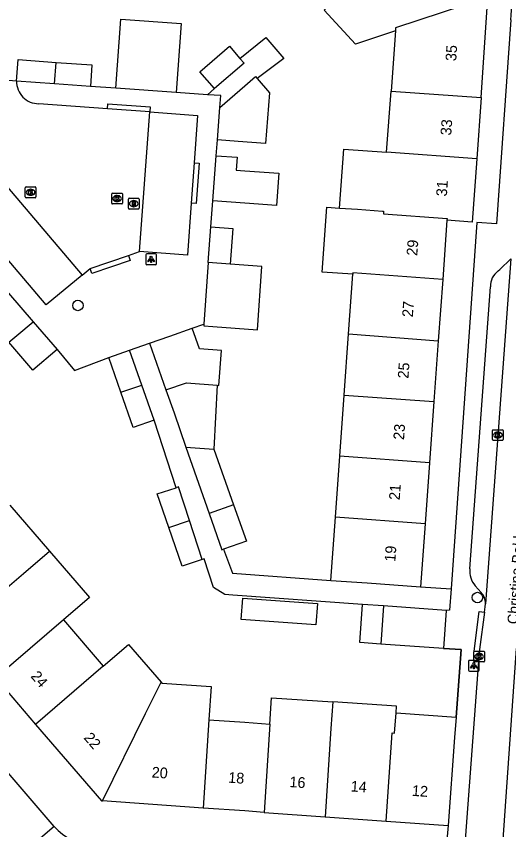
# Model space of a CAD drawing. Extents: x 160304 to 160954, y 383686 to 384161.
# Drawn here: x 160478.7 to 160524.6, y 384042.8 to 384118.4 of the extents above; entities that cross this region are included whole.
import ezdxf

# ---------------------------------------------------------------- set-up
doc = ezdxf.new("R2010")
doc.units = 0
for name, color, linetype in [('IMGEO_Boom', 7, 'Continuous'), ('IMGEO_Kolk', 7, 'Continuous'), ('IMGEO_Lichtpunt', 7, 'Continuous'), ('IMGEO_Muur', 7, 'Continuous'), ('IMGEO_Openbare_ruimte_label', 7, 'Continuous'), ('IMGEO_Pand', 7, 'Continuous'), ('IMGEO_Pand_nummerreeks', 7, 'Continuous'), ('IMGEO_Rijbaan_lokaal_open', 7, 'Continuous'), ('IMGEO_Rioolput', 7, 'Continuous'), ('IMGEO_Voetpad_open', 7, 'Continuous')]:
    doc.layers.add(name, color=color, linetype=linetype)

msp = doc.modelspace()

# ---------------------------------------------------------------- linework, layer by layer
at = {"layer": 'IMGEO_Boom'}
for centre in [(160484.478, 384091.529), (160521.654, 384064.361)]:
    msp.add_circle(centre, 0.489, dxfattribs=at)
at = {"layer": 'IMGEO_Kolk'}
for p, q in [((160479.572, 384101.627), (160479.572, 384102.479)), ((160479.647, 384102.553), (160480.499, 384102.553)), ((160480.573, 384102.479), (160480.573, 384101.627)), ((160480.083, 384101.773), (160480.058, 384101.773)), ((160480.06, 384102.333), (160480.085, 384102.333)), ((160487.623, 384101.043), (160487.623, 384101.895)), ((160487.698, 384101.969), (160488.55, 384101.969)), ((160488.111, 384101.749), (160488.136, 384101.749)), ((160488.624, 384101.895), (160488.624, 384101.043)), ((160480.499, 384101.553), (160479.647, 384101.553)), ((160488.55, 384100.969), (160487.698, 384100.969)), ((160488.134, 384101.189), (160488.109, 384101.189)), ((160523.049, 384079.049), (160523.049, 384079.901)), ((160523.124, 384079.975), (160523.976, 384079.975)), ((160523.537, 384079.755), (160523.562, 384079.755)), ((160524.05, 384079.901), (160524.05, 384079.049)), ((160523.56, 384079.195), (160523.535, 384079.195)), ((160523.976, 384078.975), (160523.124, 384078.975)), ((160521.379, 384059.374), (160522.231, 384059.374)), ((160521.304, 384058.448), (160521.304, 384059.3)), ((160521.815, 384058.594), (160521.79, 384058.594)), ((160521.792, 384059.154), (160521.817, 384059.154)), ((160522.305, 384059.3), (160522.305, 384058.448)), ((160522.231, 384058.374), (160521.379, 384058.374))]:
    msp.add_line(p, q, dxfattribs=at)
for points in [[(160479.572, 384101.627), (160479.572, 384102.479)], [(160479.647, 384102.553), (160480.499, 384102.553)], [(160480.573, 384102.479), (160480.573, 384101.627)], [(160479.893, 384102.253), (160480.016, 384102.253), (160480.016, 384102.102), (160480.146, 384102.253), (160480.31, 384102.253), (160480.164, 384102.102), (160480.317, 384101.853), (160480.165, 384101.853), (160480.08, 384102.017), (160480.016, 384101.95), (160480.016, 384101.853), (160479.893, 384101.853), (160479.893, 384102.253)], [(160487.623, 384101.043), (160487.623, 384101.895)], [(160487.698, 384101.969), (160488.55, 384101.969)], [(160488.624, 384101.895), (160488.624, 384101.043)], [(160480.499, 384101.553), (160479.647, 384101.553)], [(160488.55, 384100.969), (160487.698, 384100.969)], [(160487.944, 384101.669), (160488.067, 384101.669), (160488.067, 384101.518), (160488.197, 384101.669), (160488.361, 384101.669), (160488.215, 384101.518), (160488.368, 384101.269), (160488.216, 384101.269), (160488.131, 384101.433), (160488.067, 384101.366), (160488.067, 384101.269), (160487.944, 384101.269), (160487.944, 384101.669)], [(160523.049, 384079.049), (160523.049, 384079.901)], [(160523.124, 384079.975), (160523.976, 384079.975)], [(160524.05, 384079.901), (160524.05, 384079.049)], [(160523.37, 384079.675), (160523.493, 384079.675), (160523.493, 384079.524), (160523.623, 384079.675), (160523.787, 384079.675), (160523.641, 384079.524), (160523.794, 384079.275), (160523.642, 384079.275), (160523.557, 384079.439), (160523.493, 384079.372), (160523.493, 384079.275), (160523.37, 384079.275), (160523.37, 384079.675)], [(160523.976, 384078.975), (160523.124, 384078.975)], [(160521.379, 384059.374), (160522.231, 384059.374)], [(160521.304, 384058.448), (160521.304, 384059.3)], [(160521.625, 384059.074), (160521.748, 384059.074), (160521.748, 384058.923), (160521.878, 384059.074), (160522.042, 384059.074), (160521.896, 384058.923), (160522.049, 384058.674), (160521.897, 384058.674), (160521.812, 384058.838), (160521.748, 384058.771), (160521.748, 384058.674), (160521.625, 384058.674), (160521.625, 384059.074)], [(160522.305, 384059.3), (160522.305, 384058.448)], [(160522.231, 384058.374), (160521.379, 384058.374)]]:
    msp.add_lwpolyline(points, dxfattribs=at)
for centre, start, end in [((160479.649, 384102.477), 91.55205, 178.44795), ((160479.649, 384102.477), 91.55205, 178.44795), ((160480.497, 384102.477), 1.55205, 88.44795), ((160480.497, 384102.477), 1.55205, 88.44795), ((160487.7, 384101.893), 91.55205, 178.44795), ((160487.7, 384101.893), 91.55205, 178.44795), ((160488.548, 384101.893), 1.55205, 88.44795), ((160488.548, 384101.893), 1.55205, 88.44795), ((160479.649, 384101.629), 181.55205, 268.44795), ((160479.649, 384101.629), 181.55205, 268.44795), ((160480.497, 384101.629), 271.55205, 358.44795), ((160480.497, 384101.629), 271.55205, 358.44795), ((160487.7, 384101.045), 181.55205, 268.44795), ((160487.7, 384101.045), 181.55205, 268.44795), ((160488.548, 384101.045), 271.55205, 358.44795), ((160488.548, 384101.045), 271.55205, 358.44795), ((160523.126, 384079.899), 91.55205, 178.44795), ((160523.126, 384079.899), 91.55205, 178.44795), ((160523.974, 384079.899), 1.55205, 88.44795), ((160523.974, 384079.899), 1.55205, 88.44795), ((160523.126, 384079.051), 181.55205, 268.44795), ((160523.126, 384079.051), 181.55205, 268.44795), ((160523.974, 384079.051), 271.55205, 358.44795), ((160523.974, 384079.051), 271.55205, 358.44795), ((160521.381, 384059.298), 91.55205, 178.44795), ((160521.381, 384059.298), 91.55205, 178.44795), ((160522.229, 384059.298), 1.55205, 88.44795), ((160522.229, 384059.298), 1.55205, 88.44795), ((160521.381, 384058.45), 181.55205, 268.44795), ((160521.381, 384058.45), 181.55205, 268.44795), ((160522.229, 384058.45), 271.55205, 358.44795), ((160522.229, 384058.45), 271.55205, 358.44795)]:
    msp.add_arc(centre, 0.0765, start, end, dxfattribs=at)
for centre, major_axis, ratio, start_param, end_param in [((160480.059, 384102.053), (-0.387, 0.002), 0.722429, 4.712389, 7.853982), ((160480.084, 384102.053), (-0.39, 0.002), 0.717154, 1.570796, 4.712389), ((160488.11, 384101.469), (-0.387, 0.002), 0.722429, 4.712389, 7.853982), ((160488.135, 384101.469), (-0.39, 0.002), 0.717154, 1.570796, 4.712389), ((160523.536, 384079.475), (-0.387, 0.002), 0.722429, 4.712389, 7.853982), ((160523.561, 384079.475), (-0.39, 0.002), 0.717154, 1.570796, 4.712389), ((160521.791, 384058.874), (-0.387, 0.002), 0.722429, 4.712389, 7.853982), ((160521.816, 384058.874), (-0.39, 0.002), 0.717154, 1.570796, 4.712389)]:
    msp.add_ellipse(centre, major_axis=major_axis, ratio=ratio, start_param=start_param, end_param=end_param, dxfattribs=at)
at = {"layer": 'IMGEO_Lichtpunt'}
for p, q in [((160490.784, 384096.223), (160490.784, 384095.416)), ((160490.784, 384096.223), (160490.784, 384095.416)), ((160491.686, 384096.318), (160490.878, 384096.318)), ((160491.686, 384096.318), (160490.878, 384096.318)), ((160491.78, 384095.416), (160491.78, 384096.223)), ((160491.78, 384095.416), (160491.78, 384096.223)), ((160490.878, 384095.322), (160491.686, 384095.322)), ((160490.878, 384095.322), (160491.686, 384095.322)), ((160520.818, 384058.425), (160520.818, 384057.618)), ((160520.818, 384058.425), (160520.818, 384057.618)), ((160521.72, 384058.52), (160520.912, 384058.52)), ((160521.72, 384058.52), (160520.912, 384058.52)), ((160521.814, 384057.618), (160521.814, 384058.425)), ((160521.814, 384057.618), (160521.814, 384058.425)), ((160520.912, 384057.524), (160521.72, 384057.524)), ((160520.912, 384057.524), (160521.72, 384057.524))]:
    msp.add_line(p, q, dxfattribs=at)
for points in [[(160491.158, 384095.887), (160491.197, 384095.859), (160491.009, 384095.597), (160490.971, 384095.624), (160491.158, 384095.887)], [(160491.26, 384095.839), (160491.307, 384095.839), (160491.307, 384095.517), (160491.26, 384095.517), (160491.26, 384095.839)], [(160491.37, 384095.859), (160491.408, 384095.886), (160491.595, 384095.624), (160491.556, 384095.596), (160491.37, 384095.859)], [(160521.192, 384058.089), (160521.231, 384058.061), (160521.043, 384057.799), (160521.005, 384057.826), (160521.192, 384058.089)], [(160521.294, 384058.041), (160521.341, 384058.041), (160521.341, 384057.719), (160521.294, 384057.719), (160521.294, 384058.041)], [(160521.404, 384058.061), (160521.442, 384058.088), (160521.629, 384057.826), (160521.59, 384057.798), (160521.404, 384058.061)]]:
    msp.add_lwpolyline(points, dxfattribs=at)
for centre in [(160491.283, 384096.021), (160521.317, 384058.223)]:
    msp.add_circle(centre, 0.0994, dxfattribs=at)
for centre, start, end in [((160490.878, 384096.223), 90, 180), ((160490.878, 384096.223), 90, 180), ((160491.686, 384096.223), 0, 90), ((160491.686, 384096.223), 0, 90), ((160490.878, 384095.416), 180, 270), ((160490.878, 384095.416), 180, 270), ((160491.686, 384095.416), 270, 0), ((160491.686, 384095.416), 270, 360), ((160520.912, 384058.425), 90, 180), ((160520.912, 384058.425), 90, 180), ((160521.72, 384058.425), 0, 90), ((160521.72, 384058.425), 0, 90), ((160520.912, 384057.618), 180, 270), ((160520.912, 384057.618), 180, 270), ((160521.72, 384057.618), 270, 0), ((160521.72, 384057.618), 270, 360)]:
    msp.add_arc(centre, 0.0946, start, end, dxfattribs=at)
at = {"layer": 'IMGEO_Muur'}
msp.add_lwpolyline([(160519.66, 384053.226), (160520.14, 384059.528), (160518.484, 384059.617)], dxfattribs=at)
at = {"layer": 'IMGEO_Pand'}
for points in [[(160514.011, 384117.06), (160510.303, 384115.827), (160507.38, 384118.991), (160510.344, 384121.73), (160510.249, 384121.843)], [(160522.612, 384120.204), (160514.032, 384117.351), (160514.011, 384117.06)], [(160521.986, 384110.857), (160522.612, 384120.204)], [(160487.996, 384111.729), (160488.457, 384118.156), (160494.077, 384117.753), (160493.616, 384111.326)], [(160514.011, 384117.06), (160513.609, 384111.458)], [(160497.179, 384111.694), (160495.833, 384113.255), (160498.584, 384115.629), (160499.556, 384114.501)], [(160478.766, 384112.396), (160478.909, 384114.39), (160482.45, 384114.136)], [(160482.307, 384112.142), (160482.45, 384114.136)], [(160482.45, 384114.136), (160485.779, 384113.898), (160485.636, 384111.903)], [(160499.556, 384114.501), (160499.93, 384114.068), (160497.179, 384111.694)], [(160482.307, 384112.142), (160478.766, 384112.396)], [(160501.158, 384112.632), (160502.302, 384111.306), (160501.945, 384106.576), (160499.401, 384106.778), (160497.452, 384106.933)], [(160497.679, 384109.938), (160500, 384111.942), (160501.006, 384112.809), (160501.158, 384112.632)], [(160485.636, 384111.903), (160482.307, 384112.142)], [(160493.616, 384111.326), (160487.996, 384111.729)], [(160513.202, 384105.778), (160513.609, 384111.458)], [(160513.609, 384111.458), (160521.986, 384110.857)], [(160521.986, 384110.857), (160521.579, 384105.174)], [(160497.452, 384106.933), (160497.679, 384109.938)], [(160508.819, 384100.592), (160509.212, 384106.066), (160513.202, 384105.778)], [(160521.579, 384105.174), (160513.202, 384105.778)], [(160497.025, 384101.264), (160497.341, 384105.453)], [(160497.341, 384105.453), (160499.296, 384105.314), (160499.21, 384104.116), (160500, 384104.06), (160503.173, 384103.832), (160502.959, 384100.839), (160500, 384101.051), (160497.025, 384101.264)], [(160521.579, 384105.174), (160521.156, 384099.28), (160518.81, 384099.449)], [(160510.051, 384094.423), (160507.198, 384094.627), (160507.632, 384100.677), (160508.819, 384100.592)], [(160508.819, 384100.592), (160510.485, 384100.472), (160512.809, 384100.305), (160512.913, 384100.298), (160512.9, 384100.06), (160518.822, 384099.62), (160518.81, 384099.449)], [(160518.81, 384099.449), (160518.416, 384093.949)], [(160496.602, 384095.514), (160496.84, 384098.826)], [(160496.84, 384098.826), (160498.889, 384098.679), (160498.652, 384095.369)], [(160496.19, 384089.785), (160496.179, 384089.627), (160497.042, 384089.566), (160501.183, 384089.273), (160501.599, 384095.161), (160498.652, 384095.369)], [(160496.602, 384095.514), (160496.349, 384091.987), (160496.19, 384089.785)], [(160498.652, 384095.369), (160496.602, 384095.514)], [(160509.653, 384088.877), (160510.051, 384094.423)], [(160518.416, 384093.949), (160510.061, 384094.563), (160510.051, 384094.423)], [(160518.416, 384093.949), (160518.007, 384088.252)], [(160478.019, 384092.67), (160480.327, 384089.995)], [(160478.041, 384088.101), (160478.793, 384088.749), (160480.327, 384089.995)], [(160480.327, 384089.995), (160482.537, 384087.433)], [(160491.147, 384088.013), (160493.041, 384088.678), (160495.109, 384089.406)], [(160497.418, 384084.102), (160497.587, 384084.088), (160497.837, 384087.341), (160495.779, 384087.499), (160495.109, 384089.406)], [(160509.246, 384083.194), (160509.653, 384088.877)], [(160509.653, 384088.877), (160518.007, 384088.252)], [(160482.537, 384087.433), (160480.29, 384085.494), (160478.041, 384088.101)], [(160518.007, 384088.252), (160517.601, 384082.593)], [(160487.338, 384086.673), (160489.275, 384087.354)], [(160490.41, 384084.126), (160489.275, 384087.354)], [(160491.147, 384088.013), (160492.667, 384083.688)], [(160488.47, 384083.452), (160487.338, 384086.673)], [(160492.667, 384083.688), (160494.564, 384084.344), (160497.418, 384084.102)], [(160488.47, 384083.452), (160490.41, 384084.126)], [(160491.559, 384080.856), (160490.41, 384084.126)], [(160492.667, 384083.688), (160493.42, 384081.546), (160494.527, 384078.339)], [(160497.418, 384084.102), (160497.111, 384078.154)], [(160491.559, 384080.856), (160489.622, 384080.175), (160488.47, 384083.452)], [(160508.838, 384077.503), (160509.246, 384083.194)], [(160509.246, 384083.194), (160517.601, 384082.593)], [(160517.601, 384082.593), (160517.193, 384076.902)], [(160494.527, 384078.339), (160497.111, 384078.154)], [(160494.527, 384078.339), (160496.676, 384072.183)], [(160497.111, 384078.154), (160498.96, 384072.985)], [(160508.431, 384071.824), (160508.838, 384077.503)], [(160517.193, 384076.902), (160508.838, 384077.503)], [(160517.193, 384076.902), (160516.786, 384071.222)], [(160492.93, 384070.87), (160491.845, 384074), (160493.612, 384074.577)], [(160494.862, 384071.541), (160493.845, 384074.653), (160493.612, 384074.577)], [(160478.133, 384072.959), (160481.824, 384068.681)], [(160498.96, 384072.985), (160496.676, 384072.183)], [(160498.96, 384072.985), (160500.164, 384069.62), (160498.031, 384068.857)], [(160496.676, 384072.183), (160497.858, 384068.795), (160498.031, 384068.857)], [(160492.93, 384070.87), (160494.862, 384071.541)], [(160496.05, 384067.907), (160494.862, 384071.541)], [(160508.01, 384065.96), (160508.431, 384071.824)], [(160516.786, 384071.222), (160508.431, 384071.824)], [(160496.05, 384067.907), (160494.166, 384067.291), (160492.93, 384070.87)], [(160516.786, 384071.222), (160516.366, 384065.361)], [(160473.083, 384061.203), (160479.42, 384066.59), (160481.824, 384068.681)], [(160481.824, 384068.681), (160485.546, 384064.367), (160483.121, 384062.275)], [(160508.01, 384065.96), (160511.379, 384065.718), (160516.366, 384065.361)], [(160506.757, 384063.801), (160506.614, 384061.811), (160499.677, 384062.308), (160499.819, 384064.298), (160506.757, 384063.801)], [(160512.65, 384060.036), (160510.708, 384060.175), (160510.963, 384063.721)], [(160512.897, 384063.582), (160510.963, 384063.721)], [(160512.897, 384063.582), (160512.65, 384060.036)], [(160518.738, 384063.163), (160512.897, 384063.582)], [(160518.738, 384063.163), (160518.484, 384059.617)], [(160483.121, 384062.275), (160476.89, 384056.96), (160476.806, 384056.888)], [(160483.121, 384062.275), (160486.83, 384057.977)], [(160486.83, 384057.977), (160489.185, 384060.009), (160492.216, 384056.496)], [(160518.484, 384059.617), (160512.65, 384060.036)], [(160486.83, 384057.977), (160480.535, 384052.567)], [(160476.806, 384056.888), (160480.535, 384052.567)], [(160486.77, 384045.457), (160490.75, 384053.58), (160492.216, 384056.496)], [(160492.216, 384056.496), (160492.293, 384056.407), (160496.882, 384056.079), (160496.661, 384052.999)], [(160502.342, 384052.592), (160502.501, 384055.039), (160508.19, 384054.655)], [(160508.19, 384054.655), (160508.023, 384052.184), (160507.469, 384043.973)], [(160514.075, 384053.627), (160514.109, 384054.255), (160508.19, 384054.655)], [(160513.15, 384043.566), (160513.704, 384051.777), (160513.941, 384051.76), (160514.075, 384053.627)], [(160514.075, 384053.627), (160519.66, 384053.226)], [(160480.535, 384052.567), (160486.663, 384045.465), (160486.77, 384045.457)], [(160496.661, 384052.999), (160496.136, 384044.786)], [(160496.661, 384052.999), (160500, 384052.76), (160502.342, 384052.592)], [(160502.342, 384052.592), (160501.809, 384044.379)], [(160519.66, 384053.226), (160519.526, 384051.359), (160518.937, 384043.151)], [(160496.136, 384044.786), (160486.77, 384045.457)], [(160501.809, 384044.379), (160500, 384044.509), (160496.136, 384044.786)], [(160501.809, 384044.379), (160507.469, 384043.973)], [(160507.469, 384043.973), (160513.15, 384043.566)], [(160513.15, 384043.566), (160518.937, 384043.151)]]:
    msp.add_lwpolyline(points, dxfattribs=at)
at = {"layer": 'IMGEO_Rijbaan_lokaal_open'}
for points in [[(160478.766, 384112.396), (160474.284, 384112.752)], [(160487.225, 384109.82), (160480.83, 384110.285)], [(160491.157, 384109.534), (160487.225, 384109.82)], [(160490.217, 384096.541), (160491.157, 384109.534)], [(160474.228, 384106.839), (160484.876, 384094.347)], [(160489.177, 384096.183), (160490.217, 384096.541)], [(160485.622, 384094.958), (160489.177, 384096.183)], [(160524.75, 384095.864), (160522.403, 384063.785)], [(160484.876, 384094.347), (160485.622, 384094.958)], [(160522.315, 384062.992), (160522.383, 384063.508), (160522.403, 384063.785)], [(160522.315, 384062.992), (160521.854, 384059.515), (160521.838, 384059.295)], [(160523.983, 384040.97), (160525.298, 384059.629)], [(160520.333, 384038.909), (160521.838, 384059.295)]]:
    msp.add_lwpolyline(points, dxfattribs=at)
msp.add_arc((160480.844, 384112.363), 2.078, 179.08232, 269.62772, dxfattribs=at)
at = {"layer": 'IMGEO_Rioolput'}
for p, q in [((160489.173, 384100.569), (160489.173, 384101.421)), ((160489.248, 384101.495), (160490.1, 384101.495)), ((160489.661, 384101.275), (160489.686, 384101.275)), ((160490.174, 384101.421), (160490.174, 384100.569)), ((160490.1, 384100.495), (160489.248, 384100.495)), ((160489.684, 384100.715), (160489.659, 384100.715))]:
    msp.add_line(p, q, dxfattribs=at)
for points in [[(160489.173, 384100.569), (160489.173, 384101.421)], [(160489.248, 384101.495), (160490.1, 384101.495)], [(160489.762, 384101.193), (160489.51, 384101.195), (160489.51, 384100.795)], [(160489.51, 384100.795), (160489.634, 384100.795), (160489.634, 384100.957), (160489.645, 384100.957)], [(160489.688, 384101.114), (160489.634, 384101.114), (160489.634, 384101.033)], [(160489.634, 384101.033), (160489.686, 384101.033)], [(160489.692, 384100.928), (160489.763, 384100.795), (160489.903, 384100.795), (160489.838, 384100.921)], [(160490.174, 384101.421), (160490.174, 384100.569)], [(160490.1, 384100.495), (160489.248, 384100.495)]]:
    msp.add_lwpolyline(points, dxfattribs=at)
for centre, radius, start, end in [((160489.25, 384101.419), 0.0765, 91.55205, 178.44795), ((160489.25, 384101.419), 0.0765, 91.55205, 178.44795), ((160489.644, 384100.904), 0.0533, 26.02933, 88.69889), ((160489.67, 384101.222), 0.19, 274.7715, 282.96867), ((160489.694, 384101.018), 0.0964, 77.00612, 93.18647), ((160489.708, 384101.075), 0.0378, 276.66336, 79.67722), ((160489.761, 384101.083), 0.109, 350.36119, 89.41601), ((160489.759, 384101.083), 0.112, 277.58423, 350.98172), ((160489.743, 384100.868), 0.108, 29.51342, 73.79051), ((160490.098, 384101.419), 0.0765, 1.55205, 88.44795), ((160490.098, 384101.419), 0.0765, 1.55205, 88.44795), ((160489.25, 384100.571), 0.0765, 181.55205, 268.44795), ((160489.25, 384100.571), 0.0765, 181.55205, 268.44795), ((160490.098, 384100.571), 0.0765, 271.55205, 358.44795), ((160490.098, 384100.571), 0.0765, 271.55205, 358.44795)]:
    msp.add_arc(centre, radius, start, end, dxfattribs=at)
for centre, major_axis, ratio, start_param, end_param in [((160489.66, 384100.995), (-0.387, 0.002), 0.722429, 4.712389, 7.853982), ((160489.685, 384100.995), (-0.39, 0.002), 0.717154, 1.570796, 4.712389)]:
    msp.add_ellipse(centre, major_axis=major_axis, ratio=ratio, start_param=start_param, end_param=end_param, dxfattribs=at)
at = {"layer": 'IMGEO_Voetpad_open'}
for points in [[(160524.758, 384118.081), (160523.413, 384099.123), (160521.599, 384099.239), (160519.191, 384065.161)], [(160499.556, 384114.501), (160501.958, 384116.465), (160503.625, 384114.498), (160501.158, 384112.632)], [(160487.996, 384111.729), (160485.636, 384111.903)], [(160496.529, 384111.132), (160497.179, 384111.694)], [(160496.529, 384111.132), (160493.616, 384111.326)], [(160497.679, 384109.938), (160497.77, 384111.05), (160496.529, 384111.132)], [(160487.225, 384109.82), (160487.26, 384110.289), (160491.194, 384110.005), (160491.157, 384109.534)], [(160491.157, 384109.534), (160495.602, 384109.211), (160495.282, 384104.793)], [(160497.341, 384105.453), (160497.452, 384106.933)], [(160495.282, 384104.793), (160495.752, 384104.76), (160495.48, 384101), (160495.01, 384101.033)], [(160495.282, 384104.793), (160495.01, 384101.033)], [(160484.876, 384094.347), (160481.519, 384091.597), (160471.962, 384102.809), (160474.017, 384104.492)], [(160495.01, 384101.033), (160494.662, 384096.218), (160490.217, 384096.541)], [(160496.84, 384098.826), (160497.025, 384101.264)], [(160489.177, 384096.183), (160489.339, 384095.711), (160487.609, 384095.115), (160485.784, 384094.486), (160485.622, 384094.958)], [(160523.578, 384094.74), (160523.746, 384094.883), (160524.75, 384095.864)], [(160520.936, 384067.041), (160522.853, 384093.247)], [(160482.27, 384043.068), (160464.114, 384064.194), (160464.179, 384070.303), (160445.759, 384091.611)], [(160495.109, 384089.406), (160496.19, 384089.785)], [(160482.537, 384087.433), (160484.162, 384085.491), (160487.338, 384086.673)], [(160489.275, 384087.354), (160491.147, 384088.013)], [(160493.612, 384074.577), (160491.559, 384080.856)], [(160498.031, 384068.857), (160498.844, 384066.618), (160508.01, 384065.96)], [(160510.963, 384063.721), (160498.886, 384064.589), (160498.143, 384064.642), (160497.087, 384065.306), (160496.219, 384067.962), (160496.05, 384067.907)], [(160516.366, 384065.361), (160519.191, 384065.161)], [(160521.996, 384064.826), (160521.433, 384065.452)], [(160519.191, 384065.161), (160519.051, 384063.177), (160518.738, 384063.163)], [(160521.838, 384059.295), (160521.343, 384059.359), (160521.82, 384063.056), (160522.315, 384062.992)], [(160518.484, 384059.617), (160520.14, 384059.528), (160519.66, 384053.226)], [(160482.27, 384043.068), (160479.686, 384040.851)], [(160518.937, 384043.151), (160518.569, 384038.999)]]:
    msp.add_lwpolyline(points, dxfattribs=at)
for centre, radius, start, end in [((160515.931, 384119.178), 8.895, 352.91566, 40.19973), ((160524.61, 384093.317), 1.758, 125.93114, 182.26649), ((160523.109, 384066.848), 2.181, 174.93335, 219.80344), ((160520.886, 384063.792), 1.517, 359.73847, 42.96956), ((160485.871, 384046.121), 4.721, 220.28872, 270.68655)]:
    msp.add_arc(centre, radius, start, end, dxfattribs=at)

# ---------------------------------------------------------------- texts
at = {"layer": 'IMGEO_Openbare_ruimte_label'}
msp.add_text('Christina Bakker-van Bossestraat', height=1, rotation=85.86946, dxfattribs=at).set_placement((160525.427, 384061.851))
at = {"layer": 'IMGEO_Pand_nummerreeks'}
for s, rotation, p in [('35', 86.16712, (160519.671, 384114.231)), ('33', 85.89926, (160519.206, 384107.319)), ('31', 85.89926, (160518.799, 384101.643)), ('29', 85.89783, (160516.045, 384096.121)), ('27', 85.89783, (160515.636, 384090.412)), ('25', 85.89909, (160515.226, 384084.702)), ('23', 85.89909, (160514.817, 384078.992)), ('21', 85.89909, (160514.415, 384073.394)), ('19', 85.89909, (160514.005, 384067.662)), ('24', 310.78963, (160480.025, 384057.014)), ('22', 310.78963, (160484.965, 384051.29)), ('20', 355.90221, (160491.314, 384047.631)), ('18', 355.89849, (160498.436, 384047.147)), ('16', 355.89762, (160504.133, 384046.738)), ('14', 355.89762, (160509.833, 384046.33)), ('12', 355.89849, (160515.53, 384045.921))]:
    msp.add_text(s, height=1, rotation=rotation, dxfattribs=at).set_placement(p)

doc.saveas('drawing.dxf')
